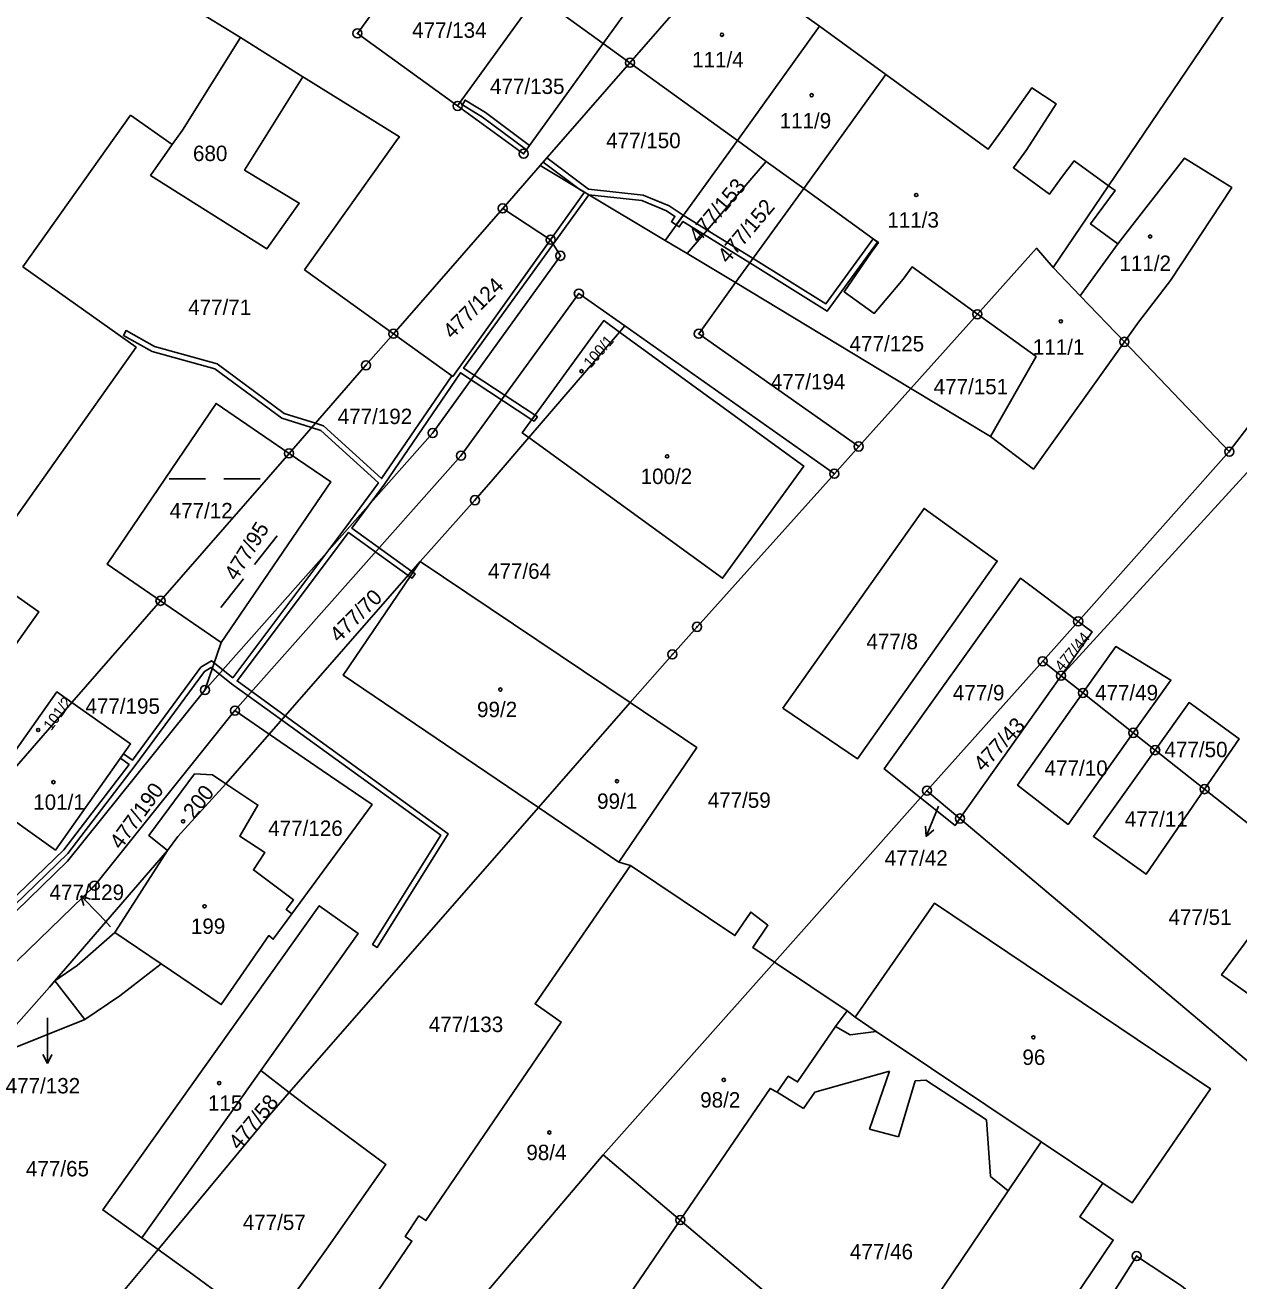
# Model space of a CAD drawing. Extents: x -758582 to -751794, y -998770 to -994350.
# Drawn here: x -754039.5 to -753905.6, y -997140.7 to -997002.2 of the extents above; entities that cross this region are included whole.
import ezdxf

# ---------------------------------------------------------------- set-up
doc = ezdxf.new("R2010")
doc.units = 0
for name, color, linetype in [('Hranice parcel', 7, 'Continuous'), ('Parcelní čísla', 7, 'Continuous'), ('Pop  PČ popisy', 7, 'Continuous'), ('Vnitřní kresba', 7, 'Continuous'), ('Věcná břemena k části', 7, 'Continuous'), ('Značky bodu BP', 7, 'Continuous'), ('Značky budov', 7, 'Continuous'), ('Značky kultur', 7, 'Continuous')]:
    doc.layers.add(name, color=color, linetype=linetype)

msp = doc.modelspace()

# ---------------------------------------------------------------- linework, layer by layer
at = {"layer": 'Hranice parcel'}
for p, q in [((-753966.6, -996991.61), (-753975.71, -997004.26)), ((-753962.49, -996994.61), (-753972.77, -997006.39)), ((-753919.98, -997019.96), (-753902.88, -996994.67)), ((-753991.77, -997011.16), (-753983, -996998.99)), ((-753983, -996998.99), (-753975.71, -997004.26)), ((-753960.91, -997014.98), (-753951.85, -997002.38)), ((-753951.85, -997002.38), (-753944.55, -997007.7)), ((-753975.71, -997004.26), (-753972.77, -997006.39)), ((-753982.68, -997017.74), (-753972.77, -997006.39)), ((-753972.77, -997006.39), (-753960.91, -997014.98)), ((-753879.42, -997013.26), (-753906.66, -997049.29)), ((-753968.89, -997026), (-753960.91, -997014.98)), ((-753960.91, -997014.98), (-753957.73, -997017.28)), ((-753957.73, -997017.28), (-753953.6, -997020.27)), ((-753986.8, -997022.46), (-753982.68, -997017.74)), ((-753953.6, -997020.27), (-753961.11, -997030.65)), ((-753919.98, -997019.96), (-753926.08, -997028.98)), ((-753998.85, -997036.28), (-753986.8, -997022.46)), ((-753981.51, -997025.91), (-753986.8, -997022.46)), ((-753968.89, -997026), (-753966.47, -997027.44)), ((-753966.47, -997027.44), (-753961.11, -997030.65)), ((-753961.11, -997030.65), (-753941.79, -997042.32)), ((-753941.79, -997042.32), (-753934.44, -997034.13)), ((-753973.32, -997035.4), (-753973.92, -997036.1)), ((-753950.22, -997051.72), (-753973.32, -997035.4)), ((-753983.93, -997047.74), (-753973.92, -997036.1)), ((-753906.66, -997049.29), (-753918.23, -997037.18)), ((-753941.79, -997042.32), (-753947.53, -997048.72)), ((-753933.01, -997047.63), (-753941.79, -997042.32)), ((-754024.54, -997065.74), (-754010.36, -997049.48)), ((-753947.53, -997048.72), (-753950.22, -997051.72)), ((-753906.66, -997049.29), (-753923.33, -997068.01)), ((-753904.31, -997051.19), (-753925.22, -997074)), ((-753995.89, -997061.4), (-754012.55, -997080.44)), ((-753972.74, -997076.96), (-753995.89, -997061.4)), ((-754034.32, -997076.96), (-754024.54, -997065.74)), ((-754024.54, -997065.74), (-754017.84, -997070.35)), ((-753927.24, -997072.4), (-753923.33, -997068.01)), ((-754017.84, -997070.35), (-754019.64, -997075.58)), ((-753940.01, -997086.68), (-753927.24, -997072.4)), ((-753925.22, -997074), (-753927.24, -997072.4)), ((-753936.37, -997089.75), (-753925.22, -997074)), ((-753922.81, -997075.9), (-753925.22, -997074)), ((-754034.32, -997076.96), (-754043.77, -997087.8)), ((-753972.74, -997076.96), (-753982.86, -997088.54)), ((-753917.25, -997080.3), (-753922.81, -997075.9)), ((-754016.33, -997077.85), (-754012.55, -997080.44)), ((-754012.55, -997080.44), (-754017.34, -997085.92)), ((-753914.84, -997082.21), (-753917.25, -997080.3)), ((-753909.39, -997086.51), (-753914.84, -997082.21)), ((-753940.72, -997087.47), (-753940.01, -997086.68)), ((-753936.37, -997089.75), (-753940.01, -997086.68)), ((-753898.66, -997095.01), (-753909.39, -997086.51)), ((-753940.72, -997087.47), (-753956.82, -997105.59)), ((-754010.34, -997119.96), (-753982.86, -997088.54)), ((-753982.86, -997088.54), (-753973.99, -997094.56)), ((-753889.02, -997129.71), (-753936.37, -997089.75)), ((-754023.76, -997093.26), (-754036.19, -997107.66)), ((-753973.99, -997094.56), (-753972.72, -997094.92)), ((-753956.82, -997105.59), (-753975.71, -997126.85)), ((-753948.79, -997110.97), (-753956.82, -997105.59)), ((-754036.19, -997107.66), (-754032.89, -997111.93)), ((-753948.79, -997110.97), (-753947.92, -997111.67)), ((-754032.89, -997111.93), (-754043.87, -997116.33)), ((-754010.34, -997119.96), (-754013.47, -997117.53)), ((-753927.42, -997125.41), (-753920.62, -997129.97)), ((-753975.71, -997126.85), (-754007.78, -997164.53)), ((-753967.21, -997134.04), (-753975.71, -997126.85)), ((-754026.59, -997135.99), (-754024.81, -997137.27)), ((-754037.66, -997152.76), (-754024.81, -997137.27))]:
    msp.add_line(p, q, dxfattribs=at)
for points in [[(-753991.77, -997011.16), (-754002.82, -997003.16), (-753994.05, -996990.99)], [(-753951.85, -997002.38), (-753953.25, -997001.36), (-753962.49, -996994.61)], [(-754015.73, -997003.63), (-754026.51, -996996.96), (-754027.38, -996996.48)], [(-754015.73, -997003.63), (-754008.83, -997007.95), (-754015.27, -997018.24), (-754009.23, -997021.87), (-754012.81, -997026.91), (-754025.64, -997018.83), (-754023.24, -997015.41)], [(-754023.24, -997015.41), (-754022.13, -997013.84), (-754015.73, -997003.63)], [(-753975.71, -997004.26), (-753984.49, -997016.43), (-753991.77, -997011.16)], [(-753944.55, -997007.7), (-753945.6, -997009.17), (-753953.6, -997020.27)], [(-753919.98, -997019.96), (-753923.78, -997017.22), (-753925.16, -997019.06), (-753926.49, -997020.88), (-753930.48, -997017.97), (-753929.01, -997015.96), (-753925.74, -997010.94), (-753928.44, -997009.15), (-753931.79, -997013.9), (-753933.27, -997015.93), (-753944.55, -997007.7)], [(-754039.71, -997028.91), (-754027.85, -997012.18), (-754023.24, -997015.41)], [(-753957.73, -997017.28), (-753964.25, -997024.86), (-753966.47, -997027.44)], [(-753918.23, -997037.18), (-753916.69, -997035.02), (-753913.15, -997030.41), (-753906.39, -997020.16), (-753911.59, -997016.92), (-753918.95, -997026.38), (-753921.97, -997024.18), (-753919.26, -997020.47), (-753919.98, -997019.96)], [(-753982.68, -997017.74), (-753977.77, -997020.68), (-753968.89, -997026)], [(-753953.6, -997020.27), (-753945.93, -997025.81), (-753945.36, -997026.23), (-753946.17, -997027.34), (-753949.15, -997031.65), (-753945.83, -997034.05), (-753943.42, -997031.2), (-753942.63, -997030.27), (-753941.64, -997028.92), (-753934.44, -997034.13)], [(-754019.64, -997075.58), (-753994.52, -997047.23), (-753980.44, -997027.69), (-753981.51, -997025.91)], [(-753998.85, -997036.28), (-753992.31, -997040.99), (-753981.51, -997025.91)], [(-753926.08, -997028.98), (-753927.92, -997026.85), (-753934.44, -997034.13)], [(-754049.22, -997076.69), (-754046.35, -997078.74), (-754037.97, -997066.94), (-754044.6, -997062.28), (-754027.23, -997037.77), (-754039.71, -997028.91)], [(-753918.23, -997037.18), (-753923.1, -997032.09), (-753926.08, -997028.98)], [(-753961.11, -997030.65), (-753965.17, -997036.29), (-753947.53, -997048.72)], [(-753973.32, -997035.4), (-753978.4, -997031.86), (-753991.4, -997049.74), (-754016.33, -997077.85)], [(-753934.44, -997034.13), (-753927.98, -997038.8), (-753933.01, -997047.63)], [(-753973.92, -997036.1), (-753975.66, -997034.84), (-753984.64, -997047.23), (-753983.93, -997047.74)], [(-754010.36, -997049.48), (-754001.88, -997039.76), (-753998.85, -997036.28)], [(-753983.93, -997047.74), (-753962.55, -997063.26), (-753953.59, -997050.88), (-753973.92, -997036.1)], [(-753933.01, -997047.63), (-753928.26, -997051.21), (-753918.23, -997037.18)], [(-754010.36, -997049.48), (-754018.42, -997043.97), (-754030.42, -997061.71), (-754024.54, -997065.74)], [(-753983.93, -997047.74), (-753987.85, -997052.31), (-753989.86, -997054.64), (-753995.89, -997061.4)], [(-754017.84, -997070.35), (-754005.77, -997052.61), (-754010.36, -997049.48)], [(-753950.22, -997051.72), (-753965.37, -997068.61), (-753968.09, -997071.65), (-753972.74, -997076.96)], [(-753955.89, -997077.57), (-753947.67, -997083.17), (-753932.25, -997061.36), (-753940.33, -997055.55), (-753955.89, -997077.57)], [(-753995.89, -997061.4), (-753997.01, -997063.05), (-754004.39, -997073.93), (-753982.86, -997088.54)], [(-753923.33, -997068.01), (-753929.7, -997063.26), (-753944.71, -997084.28), (-753940.72, -997087.47)], [(-753925.22, -997074), (-753921.8, -997069.16), (-753923.33, -997068.01)], [(-753917.25, -997080.3), (-753913.11, -997074.48), (-753919.18, -997070.79), (-753922.81, -997075.9)], [(-754046.24, -997105.57), (-754034.79, -997094.46), (-754019.64, -997075.58)], [(-754034.32, -997076.96), (-754035.97, -997075.79), (-754044.26, -997087.46), (-754043.77, -997087.8)], [(-754043.77, -997087.8), (-754036.13, -997093.24), (-754027.85, -997081.52), (-754034.32, -997076.96)], [(-753973.99, -997094.56), (-753965.39, -997081.9), (-753972.74, -997076.96)], [(-753922.81, -997075.9), (-753930.01, -997086.09), (-753924.44, -997090.4), (-753917.25, -997080.3)], [(-753909.39, -997086.51), (-753905.58, -997080.96), (-753911.09, -997076.97), (-753914.84, -997082.21)], [(-754016.33, -997077.85), (-754031.82, -997097.16), (-754054.98, -997119.61), (-754058.02, -997123.68)], [(-754012.55, -997080.44), (-754006.7, -997084.44), (-754001.2, -997088.21), (-754010.06, -997100.27)], [(-753914.84, -997082.21), (-753921.65, -997091.73), (-753915.84, -997095.9), (-753909.39, -997086.51)], [(-754017.34, -997085.92), (-754018.79, -997084.95), (-754020.79, -997084.81), (-754025.83, -997091.61), (-754023.76, -997093.26)], [(-754017.34, -997085.92), (-754022.64, -997091.72), (-754023.76, -997093.26)], [(-754010.06, -997100.27), (-754010.68, -997099.8), (-754009.87, -997098.73), (-754014.29, -997095.41), (-754013.03, -997093.5), (-754015.81, -997091.71), (-754013.8, -997088.27), (-754017.34, -997085.92)], [(-753940.72, -997087.47), (-753936.91, -997090.52), (-753936.37, -997089.75)], [(-754023.76, -997093.26), (-754027.85, -997099.62), (-754029.58, -997102.31), (-754033.74, -997105.96), (-754036.19, -997107.66)], [(-753972.72, -997094.92), (-753983.23, -997110.19), (-753980.36, -997112.2), (-753995.27, -997134.1), (-753996.04, -997133.58), (-753997.55, -997135.86), (-753996.82, -997136.36), (-754008.09, -997152.9), (-754005.19, -997154.89), (-754004.94, -997155.06), (-754010.2, -997162.92), (-754007.78, -997164.53)], [(-753956.82, -997105.59), (-753959.2, -997103.99), (-753957.54, -997101.52), (-753959.45, -997100.07), (-753961.19, -997102.66), (-753972.72, -997094.92)], [(-753898.66, -997095.01), (-753907.52, -997107), (-753895.82, -997115.27), (-753887.47, -997103.86)], [(-754013.47, -997117.53), (-754002.73, -997102.44), (-754007.04, -997099.37), (-754030.89, -997132.91), (-754026.59, -997135.99)], [(-753920.62, -997129.97), (-753917.39, -997132.14), (-753908.74, -997119.56), (-753939.17, -997099.07), (-753947.92, -997111.67)], [(-754032.89, -997111.93), (-754029.02, -997109.32), (-754024.46, -997105.76), (-754017.84, -997110.27), (-754012.61, -997102.67), (-754012.11, -997103.06), (-754010.06, -997100.27)], [(-754043.87, -997116.33), (-754036.8, -997108.35), (-754036.19, -997107.66)], [(-753967.21, -997134.04), (-753957.31, -997119.51), (-753956.53, -997119.92), (-753955.31, -997118.17), (-753954.28, -997118.8), (-753950.09, -997112.68), (-753948.79, -997110.97)], [(-753947.92, -997111.67), (-753945.6, -997113.23), (-753927.42, -997125.41)], [(-754026.59, -997135.99), (-754023.26, -997131.29), (-754019.91, -997126.58), (-754016.79, -997122.2), (-754013.47, -997117.53)], [(-754010.34, -997119.96), (-754012.51, -997122.45), (-754024.81, -997137.27)], [(-754024.81, -997137.27), (-754020.98, -997140.03), (-754012.61, -997146.21), (-754009.36, -997141.61), (-754006.04, -997137), (-754002.88, -997132.47), (-753999.69, -997127.9), (-754008.09, -997121.71), (-754010.34, -997119.96)], [(-753927.42, -997125.41), (-753931.06, -997130.8), (-753945.26, -997151.86)], [(-753935.15, -997159.49), (-753919.46, -997136.24), (-753923.13, -997133.69), (-753920.62, -997129.97)], [(-753995.31, -997168.52), (-753992.19, -997163.98), (-753992.02, -997163.73), (-753988.87, -997165.82), (-753977.61, -997149.3), (-753976.86, -997149.81), (-753975.35, -997147.62), (-753976.11, -997147.1), (-753967.21, -997134.04)], [(-753945.26, -997151.86), (-753953.43, -997145.69), (-753967.21, -997134.04)], [(-753919.98, -997170.14), (-753905.61, -997149.74), (-753912.63, -997144.13), (-753910.16, -997142.77), (-753911.94, -997141.3), (-753916.88, -997138.01), (-753932.01, -997161.86)]]:
    msp.add_lwpolyline(points, dxfattribs=at)
at = {"layer": 'Pop  PČ popisy'}
for p, q in [((-753938.96, -997088.94), (-753940.08, -997091.72)), ((-753938.74, -997088.39), (-753938.96, -997088.94)), ((-753940.08, -997091.72), (-753940.17, -997090.61)), ((-753940.08, -997091.72), (-753939.24, -997090.98)), ((-754031.25, -997100.42), (-754033.33, -997098.26)), ((-754033.33, -997098.26), (-754032.28, -997098.63)), ((-754033.33, -997098.26), (-754033, -997099.33)), ((-754030.05, -997101.69), (-754031.25, -997100.42)), ((-754037.02, -997111.72), (-754037.02, -997113.77)), ((-754037.02, -997113.77), (-754037.02, -997116.77)), ((-754037.02, -997116.77), (-754037.52, -997115.77)), ((-754037.02, -997116.77), (-754036.52, -997115.77))]:
    msp.add_line(p, q, dxfattribs=at)
at = {"layer": 'Vnitřní kresba'}
for p, q in [((-754008.83, -997007.95), (-754008.46, -997008.18)), ((-753998.4, -997014.82), (-754008.66, -997029.23)), ((-754008.66, -997029.23), (-753998.85, -997036.28)), ((-754029.58, -997102.31), (-754024.46, -997105.76)), ((-753950.09, -997112.68), (-753948.49, -997113.61)), ((-753948.49, -997113.61), (-753945.6, -997113.23)), ((-753952.38, -997119.92), (-753944.15, -997117.62)), ((-753944.15, -997117.62), (-753946.36, -997124.01)), ((-753941.31, -997118.68), (-753943.15, -997124.87)), ((-753941.31, -997118.68), (-753940.13, -997118.62)), ((-753940.13, -997118.62), (-753933.44, -997123)), ((-753956.53, -997119.92), (-753953.62, -997121.72)), ((-753953.62, -997121.72), (-753952.38, -997119.92)), ((-753946.36, -997124.01), (-753943.15, -997124.87)), ((-753933.44, -997123), (-753932.99, -997129.23)), ((-753931.06, -997130.8), (-753932.99, -997129.23))]:
    msp.add_line(p, q, dxfattribs=at)
for points in [[(-753998.4, -997014.82), (-753998.2, -997014.55), (-754008.46, -997008.18)], [(-753923.1, -997032.09), (-753922.26, -997030.93), (-753918.95, -997026.38)]]:
    msp.add_lwpolyline(points, dxfattribs=at)
at = {"layer": 'Věcná břemena k části'}
for points in [[(-753984.18, -997016), (-753983.83, -997015.51), (-753988.7, -997011.9), (-753990.94, -997010.52), (-753991.25, -997011.03), (-753989.04, -997012.4)], [(-753982.35, -997017.36), (-753978.24, -997020.4), (-753977.77, -997020.68), (-753977.3, -997020.96), (-753971.45, -997021.59), (-753968.72, -997022.72), (-753967.81, -997023.34), (-753968.2, -997023.93), (-753967.65, -997024.29), (-753966.88, -997023.22), (-753968.44, -997022.19), (-753971.3, -997021), (-753977.32, -997020.33), (-753981.95, -997016.9)], [(-753964.64, -997025.32), (-753964.25, -997024.86), (-753966.88, -997023.22), (-753967.65, -997024.29), (-753967.33, -997024.51), (-753966.92, -997023.9)], [(-753945.93, -997025.81), (-753951.16, -997032.98), (-753959.19, -997028), (-753964.25, -997024.86), (-753964.64, -997025.32), (-753959.54, -997028.48), (-753951.01, -997033.78), (-753945.45, -997026.17)], [(-754007.88, -997046.64), (-754007.45, -997046.15), (-754010.9, -997045.07), (-754018.29, -997039.62), (-754025.22, -997037.68), (-754028.34, -997035.94), (-754028.64, -997036.46), (-754025.45, -997038.24), (-754018.56, -997040.17), (-754011.17, -997045.61)], [(-753983.23, -997045.28), (-753983.58, -997045.77), (-753983.33, -997045.93), (-753982.98, -997045.45)], [(-753997.24, -997062.94), (-753997.03, -997063.09), (-753996.79, -997063.26), (-753996.45, -997062.77), (-753996.7, -997062.59), (-753996.84, -997062.49)], [(-754011.19, -997078.88), (-753993.63, -997091.59), (-754001.16, -997103.64), (-754000.65, -997103.96), (-753992.82, -997091.43), (-754010.79, -997078.43)]]:
    msp.add_lwpolyline(points, close=True, dxfattribs=at)
msp.add_lwpolyline([(-754043.03, -997101.57), (-754034.77, -997093.62), (-754027.33, -997083.92), (-754019.69, -997073.53), (-754018.96, -997073.09), (-754016.71, -997074.88), (-754011.19, -997078.88), (-754010.79, -997078.43), (-754016.1, -997074.58), (-754003.8, -997058.19), (-753997.24, -997062.94), (-753996.84, -997062.49), (-754003.45, -997057.71), (-753999.85, -997052.87), (-753991.47, -997040.58), (-753983.58, -997045.77), (-753983.23, -997045.28), (-753991.12, -997040.09), (-753977.3, -997020.96), (-753977.77, -997020.68), (-753992.31, -997040.99), (-753992.42, -997040.91), (-754000.15, -997052.25), (-754006.55, -997046.43), (-754007.45, -997046.15), (-754007.88, -997046.64), (-754006.86, -997046.96), (-754000.5, -997052.74), (-754004.11, -997057.6), (-754016.58, -997074.22), (-754018.91, -997072.36), (-754020.1, -997073.07), (-754027.64, -997083.32), (-754028.62, -997082.6), (-754028.96, -997083.09), (-754028, -997083.8), (-754035.22, -997093.22), (-754043.44, -997101.12)], dxfattribs=at)
at = {"layer": 'Značky bodu BP'}
for centre, radius in [((-754002.82, -997003.16), 0.5), ((-754002.82, -997003.16), 0.0303), ((-753972.77, -997006.39), 0.5), ((-753972.77, -997006.39), 0.0303), ((-753991.77, -997011.16), 0.5), ((-753991.77, -997011.16), 0.0303), ((-753984.49, -997016.43), 0.5), ((-753984.49, -997016.43), 0.0303), ((-753986.8, -997022.46), 0.5), ((-753986.8, -997022.46), 0.0303), ((-753981.51, -997025.91), 0.5), ((-753981.51, -997025.91), 0.0303), ((-753980.44, -997027.69), 0.5), ((-753980.44, -997027.69), 0.0303), ((-753978.4, -997031.86), 0.5), ((-753978.4, -997031.86), 0.0303), ((-753934.44, -997034.13), 0.5), ((-753934.44, -997034.13), 0.0303), ((-753998.85, -997036.28), 0.5), ((-753998.85, -997036.28), 0.0303), ((-753965.17, -997036.29), 0.5), ((-753965.17, -997036.29), 0.0303), ((-753918.23, -997037.18), 0.5), ((-753918.23, -997037.18), 0.0303), ((-754001.88, -997039.76), 0.5), ((-754001.88, -997039.76), 0.0303), ((-753994.52, -997047.23), 0.5), ((-753994.52, -997047.23), 0.0303), ((-754010.36, -997049.48), 0.5), ((-754010.36, -997049.48), 0.0303), ((-753991.4, -997049.74), 0.5), ((-753947.53, -997048.72), 0.5), ((-753947.53, -997048.72), 0.0303), ((-753906.66, -997049.29), 0.5), ((-753906.66, -997049.29), 0.0303), ((-753991.4, -997049.74), 0.0303), ((-753950.22, -997051.72), 0.5), ((-753950.22, -997051.72), 0.0303), ((-753989.86, -997054.64), 0.5), ((-753989.86, -997054.64), 0.0303), ((-754024.54, -997065.74), 0.5), ((-754024.54, -997065.74), 0.0303), ((-753923.33, -997068.01), 0.5), ((-753965.37, -997068.61), 0.5), ((-753965.37, -997068.61), 0.0303), ((-753923.33, -997068.01), 0.0303), ((-753968.09, -997071.65), 0.5), ((-753968.09, -997071.65), 0.0303), ((-753927.24, -997072.4), 0.5), ((-753927.24, -997072.4), 0.0303), ((-753925.22, -997074), 0.5), ((-753925.22, -997074), 0.0303), ((-754019.64, -997075.58), 0.5), ((-754019.64, -997075.58), 0.0303), ((-753922.81, -997075.9), 0.5), ((-753922.81, -997075.9), 0.0303), ((-754016.33, -997077.85), 0.5), ((-754016.33, -997077.85), 0.0303), ((-753917.25, -997080.3), 0.5), ((-753917.25, -997080.3), 0.0303), ((-753914.84, -997082.21), 0.5), ((-753914.84, -997082.21), 0.0303), ((-753940.01, -997086.68), 0.5), ((-753940.01, -997086.68), 0.0303), ((-753909.39, -997086.51), 0.5), ((-753909.39, -997086.51), 0.0303), ((-753936.37, -997089.75), 0.5), ((-753936.37, -997089.75), 0.0303), ((-754031.82, -997097.16), 0.5), ((-754031.82, -997097.16), 0.0303), ((-753967.21, -997134.04), 0.5), ((-753967.21, -997134.04), 0.0303), ((-753916.88, -997138.01), 0.5), ((-753916.88, -997138.01), 0.0303)]:
    msp.add_circle(centre, radius, dxfattribs=at)
at = {"layer": 'Značky budov'}
for centre in [(-753962.62, -997003.31), (-753952.73, -997009.98), (-753941.19, -997020.99), (-753915.39, -997025.56), (-753925.24, -997034.91), (-753978.11, -997040.41), (-753968.67, -997049.81), (-753987.06, -997075.53), (-754038.03, -997079.98), (-753974.19, -997085.63), (-754036.35, -997085.74), (-754022.05, -997090.06), (-754019.68, -997099.43), (-753928.27, -997113.88), (-754018.07, -997118.93), (-753962.42, -997118.58), (-753981.65, -997124.38)]:
    msp.add_circle(centre, 0.175, dxfattribs=at)
at = {"layer": 'Značky kultur'}
for p, q in [((-754023.59, -997052.27), (-754019.57, -997052.27)), ((-754017.56, -997052.27), (-754013.54, -997052.27)), ((-754014.16, -997061.73), (-754011.68, -997058.57)), ((-754017.87, -997066.48), (-754015.39, -997063.32))]:
    msp.add_line(p, q, dxfattribs=at)

# ---------------------------------------------------------------- texts
at = {"layer": 'Parcelní čísla'}
for s, p in [('477/134', (-753996.8, -997003.65)), ('111/4', (-753965.91, -997006.9)), ('477/135', (-753988.2, -997009.84)), ('111/9', (-753956.26, -997013.64)), ('477/150', (-753975.39, -997015.82)), ('680', (-754020.96, -997017.24)), ('111/3', (-753944.38, -997024.58)), ('111/2', (-753918.78, -997029.36)), ('477/71', (-754021.49, -997034.21)), ('477/125', (-753948.54, -997038.23)), ('111/1', (-753928.33, -997038.6)), ('477/194', (-753957.22, -997042.42)), ('477/151', (-753939.27, -997042.96)), ('477/192', (-754005, -997046.25)), ('100/2', (-753971.59, -997052.86)), ('477/12', (-754023.53, -997056.64)), ('477/64', (-753988.42, -997063.31)), ('477/8', (-753946.69, -997071.08)), ('477/9', (-753937.15, -997076.72)), ('477/49', (-753921.47, -997076.72)), ('477/195', (-754032.82, -997078.2)), ('99/2', (-753989.63, -997078.57)), ('477/50', (-753913.81, -997082.99)), ('477/10', (-753927.03, -997085.04)), ('99/1', (-753976.39, -997088.68)), ('477/59', (-753964.19, -997088.57)), ('101/1', (-754038.58, -997088.79)), ('477/11', (-753918.19, -997090.66)), ('477/126', (-754012.66, -997091.67)), ('477/42', (-753944.67, -997094.96)), ('477/129', (-754036.78, -997098.74)), ('199', (-754021.19, -997102.48)), ('477/51', (-753913.37, -997101.48)), ('477/133', (-753994.96, -997113.3)), ('96', (-753929.48, -997116.93)), ('477/132', (-754041.62, -997120.07)), ('98/2', (-753965.02, -997121.63)), ('115', (-754019.31, -997121.98)), ('98/4', (-753984.19, -997127.43)), ('477/65', (-754039.38, -997129.22)), ('477/57', (-754015.47, -997135.13)), ('477/46', (-753948.5, -997138.37))]:
    msp.add_text(s, height=1.7, dxfattribs=at).set_placement(p)
for s, height, rotation, p in [('477/153', 1.7, 50, (-753965.16, -997026.36)), ('477/152', 1.7, 50, (-753961.96, -997028.64)), ('477/124', 1.7, 45, (-753992.37, -997036.95)), ('100/1', 1.2, 49, (-753977.1, -997040.15)), ('477/95', 1.7, 58, (-754016.18, -997063.63)), ('477/70', 1.7, 45, (-754004.87, -997070.43)), ('477/44', 1.2, 50, (-753925.11, -997073.6)), ('101/2', 1.2, 54, (-754036.59, -997080.14)), ('477/43', 1.7, 47, (-753933.8, -997084.68)), ('477/190', 1.7, 54, (-754028.92, -997093.26)), ('200', 1.7, 52, (-754020.86, -997089.9)), ('477/58', 1.7, 50, (-754015.89, -997126.42))]:
    msp.add_text(s, height=height, rotation=rotation, dxfattribs=at).set_placement(p)

doc.saveas('drawing.dxf')
